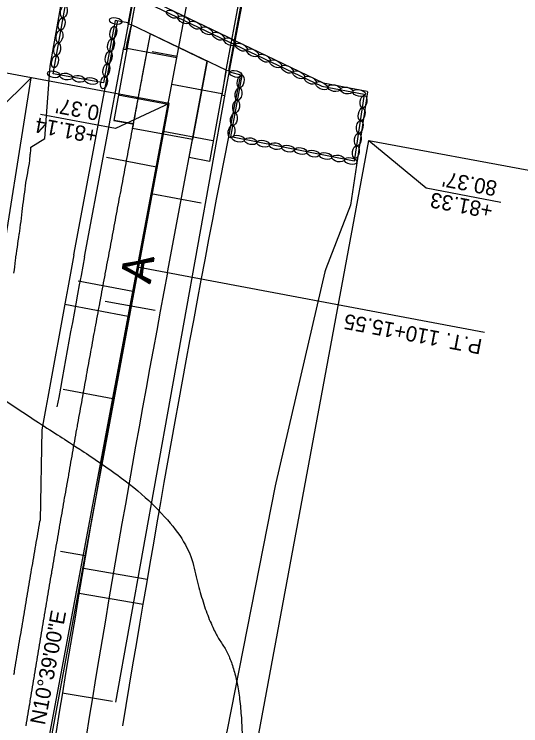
# Model space of a CAD drawing. Extents: x 674098 to 689971, y 764717 to 781049.
# Drawn here: x 688600.5 to 688800.2, y 765920.7 to 766201 of the extents above; entities that cross this region are included whole.
import ezdxf

# ---------------------------------------------------------------- set-up
doc = ezdxf.new("R2010")
doc.units = 0
for name, color, linetype in [('BRIDGE', 7, 'Continuous'), ('FLOODPLAIN', 7, 'Continuous'), ('R_Approach Slab', 7, 'Continuous'), ('R_GUARDRAIL S1', 7, 'Continuous'), ('R_GUARDRAIL S2', 7, 'Continuous'), ('R_Horz Alg', 7, 'Continuous'), ('R_Horz Alg Annot', 7, 'Continuous'), ('R_Horz Alg Station', 7, 'Continuous'), ('R_Horz Alg Station Annot', 7, 'Continuous'), ('R_No Plot', 7, 'Continuous'), ('R_Proposed Const Limits', 7, 'Continuous'), ('R_Proposed Const Limits Stage 2', 7, 'Continuous'), ('R_Proposed Riprap', 7, 'Continuous'), ('R_Proposed Riprap MOT Stage 2', 7, 'Continuous'), ('R_Proposed Road', 7, 'Continuous'), ('R_Proposed Shoulder S1', 7, 'Continuous'), ('R_ROW', 7, 'Continuous'), ('R_ROW Annot', 7, 'Continuous'), ('S_EXIST_ROW', 7, 'Continuous'), ('S_EXIST_ROW Annot', 7, 'Continuous')]:
    doc.layers.add(name, color=color, linetype=linetype)

msp = doc.modelspace()

# ---------------------------------------------------------------- linework, layer by layer
at = {"layer": 'BRIDGE'}
for p, q in [((688645.49, 766197.09), (688691.88, 766443.79)), ((688645.65, 766197.06), (688692.05, 766443.76)), ((688646.72, 766196.86), (688693.11, 766443.56)), ((688684.05, 766178.93), (688730.44, 766425.64)), ((688685.11, 766178.73), (688731.51, 766425.44)), ((688731.67, 766425.41), (688685.28, 766178.7)), ((688646.72, 766196.86), (688645.49, 766197.09)), ((688684.05, 766178.93), (688646.72, 766196.86)), ((688685.28, 766178.7), (688683.43, 766168.87)), ((688684.05, 766178.93), (688685.28, 766178.7))]:
    msp.add_line(p, q, dxfattribs=at)
for points in [[(688645.49, 766197.09), (688643.64, 766187.26), (688644.63, 766187.08), (688645.09, 766189.53), (688646.72, 766196.86)], [(688683.43, 766168.87), (688682.45, 766169.06), (688682.91, 766171.51), (688684.05, 766178.93)]]:
    msp.add_lwpolyline(points, dxfattribs=at)
at = {"layer": 'FLOODPLAIN'}
msp.add_open_spline([(687720.93, 765952.26), (687778.36, 766010.11), (687818.58, 766026.73), (687865.88, 766035.53), (687900.32, 766027.46), (687971.79, 766010.71), (687996.8, 765994.57), (688033.36, 766007.25), (688051.03, 766027.11), (688052.57, 766065.83), (688149.21, 766117.06), (688189.14, 766131.99), (688217.73, 766125.29), (688254.11, 766123.43), (688329.61, 766125.06), (688414.48, 766126.21), (688456.69, 766120.07), (688534.31, 766092.2), (688588.47, 766053.98), (688667.06, 766003.49), (688675.83, 765962.56), (688689.19, 765943.25), (688691.21, 765898.82), (688686.99, 765851.93), (688700.19, 765828.01), (688709.66, 765819.75), (688726.48, 765822.75), (688756.45, 765844.6), (688793.54, 765873.97), (688815.68, 765885.35), (688838.55, 765872.15), (688859.55, 765848.56), (688852.23, 765830.57), (688864.28, 765797.08), (688875.92, 765781.82), (688895.44, 765777.24), (688920.07, 765784), (688941.19, 765800.55), (688957.82, 765812.32), (689023.63, 765808.54), (689168.4, 765808.74), (689203.62, 765800.49), (689260.93, 765781.46), (689309.41, 765766.74), (689347.39, 765757.84), (689378.08, 765755.12), (689447.63, 765742.59), (689518.73, 765731.75), (689531.07, 765726.17), (689546.85, 765710.38)], degree=2, dxfattribs=at)
at = {"layer": 'R_Approach Slab'}
for p, q in [((688646.72, 766196.86), (688646.39, 766195.06)), ((688646.39, 766195.06), (688639.85, 766159.16)), ((688669.43, 766144.49), (688676.58, 766182.52)), ((688684.05, 766178.93), (688677.51, 766143.02)), ((688647.53, 766157.76), (688639.85, 766159.16)), ((688639.85, 766159.16), (688647.13, 766157.83)), ((688639.85, 766159.16), (688643.76, 766158.44)), ((688677.51, 766143.02), (688669.43, 766144.49))]:
    msp.add_line(p, q, dxfattribs=at)
msp.add_lwpolyline([(688647.2, 766156.01), (688654.19, 766193.26), (688676.57, 766182.52), (688670.76, 766151.58)], close=True, dxfattribs=at)
at = {"layer": 'R_GUARDRAIL S1'}
msp.add_line((688628.25, 766105.4), (688643.75, 766187.85), dxfattribs=at)
msp.add_arc((696156.98, 764689.64), 7660.69, 169.35, 169.798903, dxfattribs=at)
at = {"layer": 'R_GUARDRAIL S2'}
msp.add_lwpolyline([(688683.54, 766169.47), (688640.45, 765930.05)], dxfattribs=at)
at = {"layer": 'R_Horz Alg'}
for p, q in [((688649.13, 766101.47), (688735.51, 766560.83)), ((688649.13, 766101.47), (688735.51, 766560.83)), ((688603.33, 765857.88), (688649.13, 766101.47))]:
    msp.add_line(p, q, dxfattribs=at)
msp.add_arc((696156.98, 764689.64), 7639.44, 169.35, 173.066667, dxfattribs=at)
msp.add_arc((696156.98, 764689.64), 7639.44, 169.35, 173.066667, dxfattribs=at)
at = {"layer": 'R_Horz Alg Station'}
for points in [[(688654.91, 766186.32), (688664.74, 766184.47)], [(688649.13, 766101.47), (688785.83, 766075.77)], [(688636.44, 766088.02), (688656.11, 766084.37)], [(688618.78, 765989.46), (688628.64, 765987.76)]]:
    msp.add_lwpolyline(points, dxfattribs=at)
at = {"layer": 'R_No Plot'}
for p, q in [((688644.98, 766187.62), (688664.64, 766183.93)), ((688662.66, 766173.39), (688682.31, 766169.7)), ((688641.52, 766169.2), (688661.17, 766165.5)), ((688659.19, 766154.97), (688678.85, 766151.27)), ((688636.9, 766144.63), (688656.55, 766140.93)), ((688654.57, 766130.4), (688674.23, 766126.7)), ((688647.32, 766091.79), (688625.7, 766095.81)), ((688645.49, 766081.96), (688620.42, 766086.62)), ((688639.45, 766049.51), (688619.79, 766053.18)), ((688627.84, 765982.81), (688652.98, 765978.5)), ((688626.16, 765972.95), (688651.3, 765968.68)), ((688639.22, 765930.25), (688619.48, 765933.51))]:
    msp.add_line(p, q, dxfattribs=at)
at = {"layer": 'R_Proposed Const Limits'}
msp.add_line((688628.64, 765987.76), (688638.58, 766042.56), dxfattribs=at)
for points in [[(688612.56, 766151.99), (688614.76, 766180.47), (688621.32, 766217.54), (688623.84, 766221.24), (688687.58, 766190.63)], [(688600.44, 766098.97), (688600.6, 766100.25), (688600.75, 766101.53), (688600.91, 766102.82), (688601.06, 766104.1), (688601.15, 766104.84), (688601.21, 766105.39), (688601.4, 766106.66), (688601.59, 766107.94), (688601.77, 766109.22), (688601.94, 766110.35), (688601.96, 766110.5), (688602.14, 766111.77), (688602.33, 766113.03), (688602.51, 766114.3), (688602.58, 766114.76), (688602.7, 766115.57), (688602.88, 766116.84), (688603.06, 766118.11), (688603.24, 766119.39), (688603.38, 766120.66), (688603.52, 766121.94), (688603.65, 766123.22), (688603.79, 766124.5), (688603.82, 766124.7), (688603.91, 766125.34), (688603.97, 766125.77), (688604.14, 766127.04), (688604.31, 766128.32), (688604.47, 766129.49), (688604.49, 766129.59), (688604.66, 766130.86), (688604.83, 766132.13), (688605, 766133.4), (688605.17, 766134.63), (688605.17, 766134.68), (688605.37, 766135.94), (688605.6, 766137.21), (688605.84, 766138.47), (688606.07, 766139.73), (688606.3, 766140.99), (688606.53, 766142.25), (688606.65, 766143.53), (688606.74, 766144.5), (688606.77, 766144.81), (688606.86, 766145.75), (688606.89, 766146.09), (688607.02, 766147.38), (688607.14, 766148.66), (688612.56, 766151.99)]]:
    msp.add_lwpolyline(points, dxfattribs=at)
at = {"layer": 'R_Proposed Const Limits Stage 2'}
for points in [[(688687.52, 766190.66), (688722.35, 766173.94), (688739.62, 766170.71)], [(688739.6, 766170.7), (688739.78, 766170.36), (688733.09, 766125.83), (688723.38, 766100.71), (688722.97, 766099.48), (688703.6, 766016.4), (688703.35, 766015.16), (688684.44, 765919.13), (688684.2, 765917.9), (688672.72, 765859.42), (688671.72, 765854.17), (688661.69, 765795.57), (688660.89, 765791), (688648.95, 765726.45), (688648.45, 765722.64), (688648.26, 765718.66), (688658.99, 765713.26), (688656.07, 765697.51), (688642.73, 765693.37), (688632.18, 765651.68), (688630.7, 765644.89), (688619.68, 765575.99), (688618.83, 765570.71), (688614.85, 765546.36)]]:
    msp.add_lwpolyline(points, dxfattribs=at)
at = {"layer": 'R_Proposed Riprap'}
msp.add_lwpolyline([(688645.25, 766197.58), (688640.33, 766198.51), (688635.71, 766173.92), (688615.91, 766177.52), (688622.83, 766216.61), (688624.5, 766219.15), (688721.7, 766172.67), (688738.5, 766169.44), (688734.47, 766143.07), (688685.96, 766152.66), (688690.41, 766176.89), (688685.52, 766178.22)], dxfattribs=at)
for centre, major_axis in [((688620.11, 766202.07), (-0.44, -2.46)), ((688662.83, 766200.98), (-2.26, 1.08)), ((688619.23, 766197.13), (-0.44, -2.46)), ((688640.53, 766198.32), (2.46, -0.46)), ((688667.36, 766198.82), (-2.26, 1.08)), ((688671.89, 766196.65), (-2.26, 1.08)), ((688639.59, 766193.78), (0.46, 2.46)), ((688676.42, 766194.49), (-2.26, 1.08)), ((688618.36, 766192.19), (-0.44, -2.46)), ((688680.95, 766192.32), (-2.26, 1.08)), ((688617.48, 766187.24), (-0.44, -2.46)), ((688638.67, 766188.85), (0.46, 2.46)), ((688685.48, 766190.16), (-2.26, 1.08)), ((688616.61, 766182.3), (-0.44, -2.46)), ((688637.74, 766183.91), (0.46, 2.46)), ((688636.81, 766178.98), (0.46, 2.46)), ((688616.08, 766177.34), (2.46, -0.45)), ((688621.02, 766176.44), (2.46, -0.45)), ((688625.96, 766175.54), (2.46, -0.45)), ((688630.89, 766174.65), (2.46, -0.45)), ((688635.88, 766174.05), (0.46, 2.46))]:
    msp.add_ellipse(centre, major_axis=major_axis, ratio=0.517889, dxfattribs=at)
at = {"layer": 'R_Proposed Riprap MOT Stage 2'}
for centre, major_axis in [((688690.01, 766187.99), (-2.26, 1.08)), ((688694.53, 766185.82), (-2.26, 1.08)), ((688699.06, 766183.66), (-2.26, 1.08)), ((688703.59, 766181.49), (-2.26, 1.08)), ((688687.9, 766177.42), (2.41, -0.66)), ((688708.12, 766179.33), (-2.26, 1.08)), ((688712.65, 766177.16), (-2.26, 1.08)), ((688689.81, 766174.49), (-0.45, -2.46)), ((688717.18, 766175), (-2.26, 1.08)), ((688721.71, 766172.83), (-2.26, 1.08)), ((688726.6, 766171.88), (-2.46, 0.47)), ((688688.91, 766169.55), (-0.45, -2.46)), ((688731.53, 766170.93), (-2.46, 0.47)), ((688736.46, 766169.99), (-2.46, 0.47)), ((688688, 766164.62), (-0.45, -2.46)), ((688738.21, 766166.54), (0.38, 2.47)), ((688687.1, 766159.68), (-0.45, -2.46)), ((688737.45, 766161.58), (0.38, 2.47)), ((688736.69, 766156.62), (0.38, 2.47)), ((688686.19, 766154.74), (-0.45, -2.46)), ((688688.81, 766151.94), (2.45, -0.48)), ((688735.93, 766151.66), (0.38, 2.47)), ((688693.73, 766150.97), (2.45, -0.48)), ((688698.66, 766150), (2.45, -0.48)), ((688703.58, 766149.02), (2.45, -0.48)), ((688708.51, 766148.05), (2.45, -0.48)), ((688713.43, 766147.08), (2.45, -0.48)), ((688718.36, 766146.1), (2.45, -0.48)), ((688735.18, 766146.69), (0.38, 2.47)), ((688723.28, 766145.13), (2.45, -0.48)), ((688728.21, 766144.16), (2.45, -0.48)), ((688733.13, 766143.18), (2.45, -0.48))]:
    msp.add_ellipse(centre, major_axis=major_axis, ratio=0.517889, dxfattribs=at)
at = {"layer": 'R_Proposed Road'}
msp.add_line((688660.93, 766099.26), (688676.58, 766182.52), dxfattribs=at)
msp.add_lwpolyline([(688605.24, 765920.66), (688605.44, 765921.84), (688605.63, 765923.02), (688605.82, 765924.2), (688606.02, 765925.38), (688606.21, 765926.56), (688606.4, 765927.75), (688606.6, 765928.93), (688606.63, 765929.11), (688606.79, 765930.11), (688606.86, 765930.53), (688606.98, 765931.29), (688607.18, 765932.47), (688607.37, 765933.65), (688607.57, 765934.83), (688607.76, 765936.01), (688607.96, 765937.2), (688608.15, 765938.38), (688608.35, 765939.56), (688608.49, 765940.41), (688608.54, 765940.74), (688608.74, 765941.92), (688608.94, 765943.1), (688609.13, 765944.28), (688609.33, 765945.46), (688609.52, 765946.6), (688609.53, 765946.64), (688609.72, 765947.82), (688609.92, 765949), (688610.12, 765950.19), (688610.13, 765950.29), (688610.31, 765951.37), (688610.51, 765952.55), (688610.71, 765953.73), (688610.91, 765954.91), (688611.1, 765956.09), (688611.3, 765957.27), (688611.5, 765958.45), (688611.7, 765959.63), (688611.79, 765960.17), (688611.9, 765960.81), (688612.1, 765961.99), (688612.3, 765963.17), (688612.45, 765964.08), (688612.5, 765964.35), (688612.7, 765965.53), (688612.9, 765966.71), (688613.1, 765967.89), (688613.3, 765969.07), (688613.46, 765970.05), (688613.5, 765970.25), (688613.7, 765971.43), (688613.9, 765972.61), (688614.1, 765973.79), (688614.3, 765974.97), (688614.5, 765976.15), (688614.7, 765977.33), (688614.9, 765978.51), (688615.1, 765979.69), (688615.14, 765979.92), (688615.31, 765980.87), (688615.42, 765981.55), (688615.51, 765982.05), (688615.71, 765983.23), (688615.91, 765984.41), (688616.12, 765985.59), (688616.32, 765986.77), (688616.52, 765987.95), (688616.73, 765989.13), (688616.84, 765989.79), (688616.93, 765990.31), (688617.13, 765991.49), (688617.34, 765992.67), (688617.54, 765993.85), (688617.74, 765995.03), (688617.95, 765996.21), (688618.15, 765997.39), (688618.36, 765998.57), (688618.44, 765999.02), (688618.55, 765999.66), (688618.56, 765999.75), (688618.77, 766000.93), (688618.97, 766002.11), (688619.18, 766003.29), (688619.38, 766004.47), (688619.59, 766005.65), (688619.8, 766006.83), (688620, 766008), (688620.21, 766009.18), (688620.27, 766009.53), (688620.41, 766010.36), (688620.62, 766011.54), (688620.83, 766012.72), (688621.04, 766013.9), (688621.24, 766015.08), (688621.45, 766016.26), (688621.49, 766016.48), (688621.66, 766017.44), (688621.87, 766018.62), (688622, 766019.39), (688622.07, 766019.8), (688622.28, 766020.97), (688622.49, 766022.15), (688622.7, 766023.33), (688622.91, 766024.51), (688623.12, 766025.69), (688623.33, 766026.87), (688623.54, 766028.05), (688623.74, 766029.23), (688623.75, 766029.25), (688623.95, 766030.4), (688624.16, 766031.58), (688624.37, 766032.76), (688624.58, 766033.94), (688624.79, 766035.12), (688625.01, 766036.3), (688625.22, 766037.48), (688625.43, 766038.65), (688625.51, 766039.11), (688625.64, 766039.83), (688625.85, 766041.01), (688626.06, 766042.19), (688626.27, 766043.37), (688626.48, 766044.55), (688626.7, 766045.72), (688626.91, 766046.9), (688627.12, 766048.08), (688627.28, 766048.97), (688627.33, 766049.26), (688627.55, 766050.44), (688627.72, 766051.39), (688627.76, 766051.61), (688627.97, 766052.79), (688628.19, 766053.97), (688628.4, 766055.15), (688628.61, 766056.33), (688628.83, 766057.5), (688629.04, 766058.68), (688629.07, 766058.83), (688629.26, 766059.86), (688629.47, 766061.04), (688629.69, 766062.21), (688629.9, 766063.39), (688630.12, 766064.57), (688630.33, 766065.75), (688630.55, 766066.92), (688630.76, 766068.1), (688630.87, 766068.68), (688630.89, 766068.83), (688630.98, 766069.28), (688631.19, 766070.46), (688631.41, 766071.63), (688631.63, 766072.81), (688631.84, 766073.99), (688632.06, 766075.17), (688632.28, 766076.34), (688632.49, 766077.52), (688632.68, 766078.53), (688632.71, 766078.7), (688632.93, 766079.88), (688633.14, 766081.05), (688633.36, 766082.23), (688633.58, 766083.41), (688633.8, 766084.58), (688634.02, 766085.76), (688634.11, 766086.26), (688634.24, 766086.94), (688634.45, 766088.12), (688634.5, 766088.38), (688634.67, 766089.29), (688634.89, 766090.47), (688635.11, 766091.65), (688635.33, 766092.82), (688635.55, 766094), (688635.77, 766095.18), (688635.99, 766096.35), (688636.21, 766097.53), (688636.34, 766098.23), (688636.43, 766098.71), (688636.65, 766099.88), (688636.87, 766101.06), (688637.09, 766102.24), (688637.31, 766103.41), (688637.54, 766104.59), (688637.76, 766105.76), (688637.98, 766106.94), (688638.42, 766109.29), (688638.64, 766110.46), (688638.86, 766111.64), (688639.08, 766112.81), (688639.3, 766113.99), (688639.52, 766115.16), (688639.74, 766116.33), (688639.97, 766117.51), (688640.19, 766118.68), (688640.41, 766119.86), (688640.63, 766121.03), (688640.85, 766122.21), (688641.07, 766123.38), (688641.29, 766124.56), (688641.51, 766125.73), (688641.73, 766126.91), (688641.95, 766128.08), (688642.17, 766129.26), (688642.4, 766130.43), (688642.62, 766131.61), (688642.84, 766132.78), (688643.06, 766133.95), (688643.28, 766135.13), (688643.5, 766136.3), (688643.72, 766137.48), (688643.94, 766138.65), (688644.16, 766139.83), (688644.38, 766141), (688644.6, 766142.18), (688644.82, 766143.35), (688645.05, 766144.53), (688645.27, 766145.7), (688645.49, 766146.88), (688645.71, 766148.05), (688645.93, 766149.23), (688646.15, 766150.4), (688646.37, 766151.57), (688646.59, 766152.75), (688646.81, 766153.92), (688647.03, 766155.09), (688647.25, 766156.27), (688647.48, 766157.45), (688647.7, 766158.62), (688647.92, 766159.8), (688648.14, 766160.97), (688648.36, 766162.15), (688648.58, 766163.32), (688648.8, 766164.5), (688649.02, 766165.67), (688649.24, 766166.85), (688649.46, 766168.02), (688649.68, 766169.19), (688649.91, 766170.37), (688650.13, 766171.54), (688650.35, 766172.72), (688650.57, 766173.89), (688650.79, 766175.07), (688651.01, 766176.24), (688654.21, 766193.26)], dxfattribs=at)
msp.add_arc((696156.98, 764689.64), 7627.44, 169.35, 173.066667, dxfattribs=at)
at = {"layer": 'R_Proposed Shoulder S1'}
for p, q in [((688624.07, 766106.19), (688641.43, 766198.47)), ((688611.44, 766037.34), (688610.76, 766001.63))]:
    msp.add_line(p, q, dxfattribs=at)
msp.add_lwpolyline([(688600.45, 765940.87), (688600.59, 765941.72), (688600.65, 765942.05), (688600.84, 765943.23), (688601.04, 765944.41), (688601.23, 765945.59), (688601.43, 765946.78), (688601.62, 765947.91), (688601.63, 765947.96), (688601.82, 765949.14), (688602.02, 765950.32), (688602.22, 765951.5), (688602.24, 765951.61), (688602.42, 765952.69), (688602.61, 765953.87), (688602.81, 765955.05), (688603.01, 765956.23), (688603.21, 765957.41), (688603.41, 765958.6), (688603.61, 765959.78), (688603.8, 765960.96), (688603.9, 765961.5), (688604, 765962.14), (688604.2, 765963.32), (688604.4, 765964.51), (688604.55, 765965.41), (688604.6, 765965.69), (688604.8, 765966.87), (688605, 765968.05), (688605.2, 765969.23), (688605.4, 765970.41), (688605.57, 765971.39), (688605.6, 765971.59), (688605.8, 765972.78), (688606, 765973.96), (688606.2, 765975.14), (688606.41, 765976.32), (688606.61, 765977.5), (688606.81, 765978.68), (688607.01, 765979.86), (688607.21, 765981.05), (688607.25, 765981.27), (688607.41, 765982.23), (688607.53, 765982.91), (688607.62, 765983.41), (688607.82, 765984.59), (688608.02, 765985.77), (688608.22, 765986.95), (688608.43, 765988.13), (688608.63, 765989.31), (688608.83, 765990.49), (688608.95, 765991.15), (688609.04, 765991.67), (688609.24, 765992.86), (688609.45, 765994.04), (688609.65, 765995.22), (688609.85, 765996.4), (688610.06, 765997.58), (688610.26, 765998.76), (688610.47, 765999.94), (688610.55, 766000.39), (688610.66, 766001.03), (688610.67, 766001.12), (688610.76, 766001.63)], dxfattribs=at)
for radius, start, end in [(7613.94, 168.743915, 170.695122), (7664.94, 169.35, 169.873736)]:
    msp.add_arc((696156.98, 764689.64), radius, start, end, dxfattribs=at)
at = {"layer": 'R_ROW'}
msp.add_line((688562.91, 765896.96), (688607.18, 766175.98), dxfattribs=at)
at = {"layer": 'R_ROW Annot'}
msp.add_lwpolyline([(688607.18, 766175.98), (688593.89, 766162.98), (688564.4, 766168.52)], dxfattribs=at)
at = {"layer": 'S_EXIST_ROW'}
for p, q in [((688661.62, 766165.87), (688405.98, 766213.31)), ((688514.64, 765373.87), (688661.62, 766165.87)), ((688571.89, 765243.87), (688740.27, 766151.28)), ((688740.27, 766151.28), (688897.59, 766122.08))]:
    msp.add_line(p, q, dxfattribs=at)
at = {"layer": 'S_EXIST_ROW Annot'}
for points in [[(688661.62, 766165.87), (688640.41, 766155.99), (688610.93, 766161.54)], [(688740.27, 766151.28), (688762.87, 766132.57), (688792.36, 766127.02)]]:
    msp.add_lwpolyline(points, dxfattribs=at)

# ---------------------------------------------------------------- texts
at = {"layer": 'R_Horz Alg'}
for rotation, p in [(79.35, (688653.92, 766094.47)), (83.3627, (688654.4, 766094.82))]:
    msp.add_text('A', height=12, rotation=rotation, dxfattribs=at).set_placement(p)
at = {"layer": 'R_Horz Alg Annot'}
msp.add_text('N10%%d39\'00"E', height=6, rotation=79.35, dxfattribs=at).set_placement((688612.63, 765920.78))
at = {"layer": 'R_Horz Alg Station Annot'}
msp.add_text('P.T. 110+15.55', height=6, rotation=169.35, dxfattribs=at).set_placement((688785.27, 766072.84))
at = {"layer": 'S_EXIST_ROW Annot'}
for s, p in [("0.37'", (688634.45, 766164.87)), ('+81.14', (688633.81, 766155.83)), ("80.37'", (688791.18, 766135.12)), ('+81.33', (688789.52, 766126.28))]:
    msp.add_text(s, height=6, rotation=169.35, dxfattribs=at).set_placement(p)

doc.saveas('drawing.dxf')
